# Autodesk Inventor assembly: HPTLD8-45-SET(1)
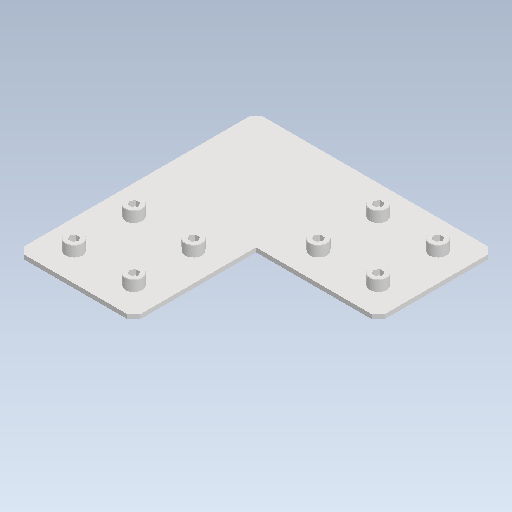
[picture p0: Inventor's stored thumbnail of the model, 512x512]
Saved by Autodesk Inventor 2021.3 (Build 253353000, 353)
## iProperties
Created: 2022-02
Part Number: HPTLD8-45-SET(1)
Document SubType Name: Assembly
Designer: kengo
Author: kengo
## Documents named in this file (4)
- C:\Users\kengo\Documents\S2S_frame\SDC345\frame_misumi_ver12\HPTLD8-45-SET(1).iam
- C:\Users\kengo\Documents\S2S_frame\SDC345\frame_misumi_ver12\HPTLD8-45.ipt
- C:\Users\kengo\Documents\S2S_frame\SDC345\frame_misumi_ver12\HNTT8-8.ipt
- C:\Users\kengo\Documents\S2S_frame\SDC345\frame_misumi_ver12\CBM8-15.ipt
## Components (17 placed, 3 different names)
1. HPTLD8-45
2. HNTT8-8
3. CBM8-15
4. HNTT8-8:1
5. CBM8-15:1
6. HNTT8-8:2
7. CBM8-15:2
8. HNTT8-8:3
9. CBM8-15:3
10. HNTT8-8:4
11. CBM8-15:4
12. HNTT8-8:5
13. CBM8-15:5
14. HNTT8-8:6
15. CBM8-15:6
16. HNTT8-8:7
17. CBM8-15:7
